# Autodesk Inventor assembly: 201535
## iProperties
Created: 2007-12
Part Number: 201535
Document SubType Name: Assembly
Designer: MM
Mass: 2432.15 g
Surface Area: 2875.32 cm^2
Volume: 309.75 cm^3
Density: 7.85198 g/cm^3
Description: BOTTOM GUIDE RAIL ASSEMBLY
Component Category: Lower Component
Author: MM
